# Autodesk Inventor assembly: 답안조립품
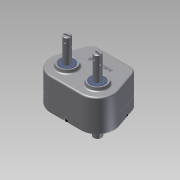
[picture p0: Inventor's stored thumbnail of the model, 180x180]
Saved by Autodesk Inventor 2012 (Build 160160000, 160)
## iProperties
Created: 2014-12
Part Number: 답안조립품
Document SubType Name: Assembly
Designer: Administrator
Author: Administrator
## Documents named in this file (14)
- C:\Documents and Settings\Administrator\바탕 화면\441208V1032 (2)\답안조립품.iam
- C:\Documents and Settings\Administrator\바탕 화면\441208V1032 (2)\본체.ipt
- C:\Documents and Settings\Administrator\바탕 화면\441208V1032 (2)\커버.ipt
- C:\Documents and Settings\Administrator\바탕 화면\441208V1032 (2)\오일시일-D-15.ipt
- C:\Documents and Settings\Administrator\바탕 화면\441208V1032 (2)\오일시일-D-17.ipt
- C:\Documents and Settings\Administrator\바탕 화면\441208V1032 (2)\베어링- 6203.ipt
- C:\Documents and Settings\Administrator\바탕 화면\441208V1032 (2)\베어링- 6202.ipt
- C:\Documents and Settings\Administrator\바탕 화면\441208V1032 (2)\메인축.ipt
- C:\Documents and Settings\Administrator\바탕 화면\441208V1032 (2)\키5x5.ipt
- C:\Documents and Settings\Administrator\바탕 화면\441208V1032 (2)\메인기어.ipt
- C:\Documents and Settings\Administrator\바탕 화면\441208V1032 (2)\서브축.ipt
- C:\Documents and Settings\Administrator\바탕 화면\441208V1032 (2)\멈춤링.ipt
- C:\Documents and Settings\Administrator\바탕 화면\441208V1032 (2)\서브기어.ipt
- C:\Documents and Settings\Administrator\바탕 화면\441208V1032 (2)\M 5 x 35.ipt
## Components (15 placed, 6 different names)
1. KS B 2804 D D - 15 30 7:1
2. KS B 2804 D D - 15 30 7:2
3. KS B 2804 D D - 17 30 8:1
4. KS B 2023 6203 - 17 x 40 x 12:1
5. KS B 2023 6203 - 17 x 40 x 12:2
6. KS B 2023 6203 - 17 x 40 x 12:3
7. KS B 2023 6203 - 17 x 40 x 12:4
8. KS B 2023 6202 - 15 x 35 x 11:1
9. KS B 2023 6202 - 15 x 35 x 11:2
10. KS B 1336 17 x 1:1
11. KS B 1336 17 x 1:2
12. KS B 1336 17 x 1:3
13. KS B 1003 - 미터 M 5 x 35:1
14. KS B 1003 - 미터 M 5 x 35:2
15. KS B 1003 - 미터 M 5 x 35:3
